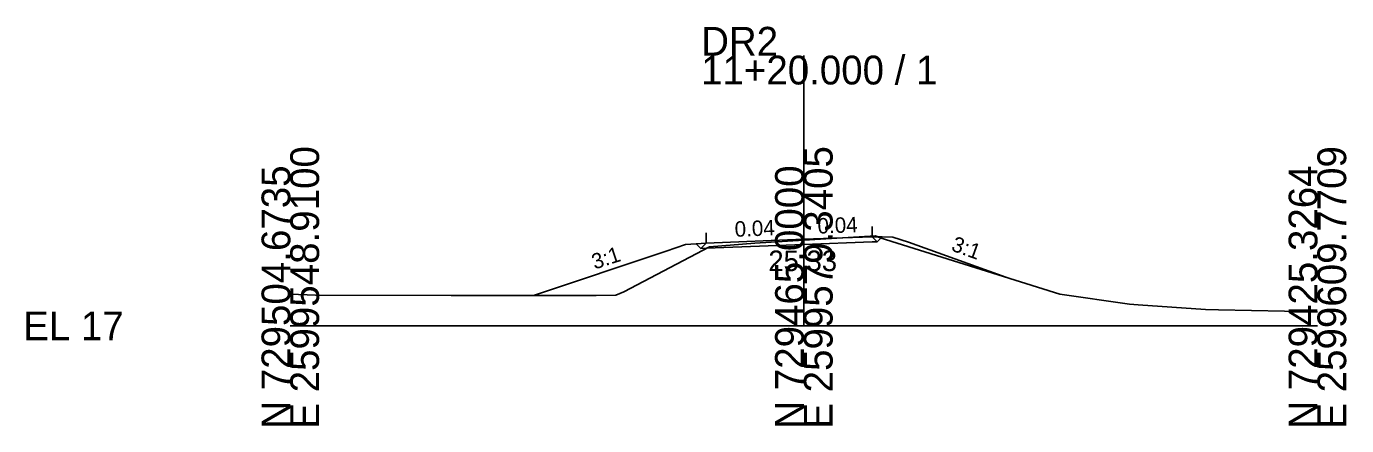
# Model space of a CAD drawing. Extents: x -26 to 1162, y -10 to 9515.
# Drawn here: x -25.7 to 102.8, y 5990.3 to 6029.1 of the extents above; entities that cross this region are included whole.
import ezdxf

# ---------------------------------------------------------------- set-up
doc = ezdxf.new("R2010")
doc.units = 0
for name, color, linetype in [('Exist Cross Section Cell', 7, 'Continuous'), ('Exist XS Center Line Elevation Label', 7, 'Continuous'), ('Exist XS Ground Line', 7, 'Continuous'), ('Prop XS Dump Level', 7, 'Continuous'), ('Prop XS EOT Tick Mark', 7, 'Continuous'), ('Prop XS Finish Grade', 7, 'Continuous'), ('Prop XS Finish Grade Earthwork', 7, 'Continuous'), ('Prop XS Finish Grade Pavement', 7, 'Continuous'), ('Prop XS Pvmt Edge Slope', 7, 'Continuous'), ('Prop XS SE Text', 7, 'Continuous'), ('Prop XS Side Slope Text', 7, 'Continuous'), ('Prop XS Subgrade Earthwork', 7, 'Continuous')]:
    doc.layers.add(name, color=color, linetype=linetype)

msp = doc.modelspace()

# ---------------------------------------------------------------- linework, layer by layer
at = {"layer": 'Exist Cross Section Cell'}
for p, q in [((50, 6000), (50, 6026.28)), ((0, 6000), (50, 6000)), ((50, 6000), (100, 6000))]:
    msp.add_line(p, q, dxfattribs=at)
at = {"layer": 'Exist XS Ground Line'}
msp.add_lwpolyline([(0, 6003.09), (2.45, 6002.98), (15.67, 6002.95), (29.77, 6002.96), (31.69, 6002.99), (32.46, 6003.3), (40.8, 6007.68), (45.22, 6008.03), (50, 6008.33), (56.44, 6008.73), (56.96, 6008.76), (57.42, 6008.58), (74.93, 6003.07), (81.71, 6002.11), (82.56, 6002.05), (89.09, 6001.58), (90.38, 6001.56), (100, 6001.38)], dxfattribs=at)
at = {"layer": 'Prop XS Dump Level'}
for p, q in [((40.5, 6008.06), (50, 6008.42)), ((50, 6008.42), (56.65, 6008.67))]:
    msp.add_line(p, q, dxfattribs=at)
at = {"layer": 'Prop XS EOT Tick Mark'}
for p, q in [((40.5, 6008.06), (40.5, 6009.06)), ((56.65, 6008.67), (56.65, 6009.67))]:
    msp.add_line(p, q, dxfattribs=at)
at = {"layer": 'Prop XS Finish Grade'}
for p, q in [((40.5, 6008.06), (39.53, 6007.98)), ((56.65, 6008.67), (57.61, 6008.65))]:
    msp.add_line(p, q, dxfattribs=at)
at = {"layer": 'Prop XS Finish Grade Earthwork'}
for p, q in [((38.49, 6007.9), (36.61, 6007.27)), ((39.53, 6007.98), (38.49, 6007.9)), ((57.61, 6008.65), (58.67, 6008.63)), ((58.67, 6008.63), (60.18, 6008.13)), ((60.18, 6008.13), (69.66, 6004.73)), ((36.61, 6007.27), (23.68, 6002.96))]:
    msp.add_line(p, q, dxfattribs=at)
at = {"layer": 'Prop XS Finish Grade Pavement'}
for p, q in [((40.5, 6008.06), (50, 6008.42)), ((50, 6008.42), (56.65, 6008.67))]:
    msp.add_line(p, q, dxfattribs=at)
at = {"layer": 'Prop XS Pvmt Edge Slope'}
for p, q in [((39.98, 6007.54), (39.53, 6007.98)), ((40.5, 6008.06), (39.98, 6007.54)), ((56.65, 6008.67), (57.14, 6008.19)), ((57.14, 6008.19), (57.61, 6008.65))]:
    msp.add_line(p, q, dxfattribs=at)
at = {"layer": 'Prop XS Subgrade Earthwork'}
for p, q in [((39.98, 6007.54), (39.53, 6007.98)), ((50, 6007.92), (40.5, 6007.56)), ((56.65, 6008.17), (50, 6007.92)), ((56.65, 6008.17), (57.14, 6008.19)), ((57.14, 6008.19), (57.61, 6008.65)), ((40.5, 6007.56), (39.98, 6007.54))]:
    msp.add_line(p, q, dxfattribs=at)

# ---------------------------------------------------------------- texts
at = {"layer": 'Exist Cross Section Cell'}
for s, p in [('DR2', (40, 6026.28)), ('11+20.000 / 1', (40, 6023.48)), ('EL 17', (-26, 5998.6))]:
    msp.add_text(s, height=2.8, dxfattribs=at).set_placement(p)
for s, p in [('E 2599548.9100', (2.8, 5990)), ('E 2599579.3405', (52.8, 5990)), ('E 2599609.7709', (102.8, 5990)), ('N 729504.6735', (0, 5990)), ('N 729465.0000', (50, 5990)), ('N 729425.3264', (100, 5990))]:
    msp.add_text(s, height=2.8, rotation=90, dxfattribs=at).set_placement(p)
at = {"layer": 'Exist XS Center Line Elevation Label'}
msp.add_text('25.33', height=2, dxfattribs=at).set_placement((46.54, 6005.33))
at = {"layer": 'Prop XS Dump Level'}
for p in [(38.49, 6007.86), (58.67, 6008.59)]:
    msp.add_text('Case1', height=0.04, dxfattribs=at).set_placement(p)
at = {"layer": 'Prop XS SE Text'}
for p in [(43.29, 6008.66), (51.36, 6008.97)]:
    msp.add_text('0.04', height=1.5, rotation=2.1854, dxfattribs=at).set_placement(p)
at = {"layer": 'Prop XS Side Slope Text'}
for rotation, p in [(18.1082, (29.63, 6005.47)), (340.3993, (64.26, 6007.35))]:
    msp.add_text('3:1', height=1.5, rotation=rotation, dxfattribs=at).set_placement(p)

doc.saveas('drawing.dxf')
